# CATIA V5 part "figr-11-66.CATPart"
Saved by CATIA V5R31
Part number: Part2
Bounding box of the stored display mesh (mm): x -101 to 134, y -101.296 to 100.099, z -60.219 to 83.072
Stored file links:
  D:\PROJECTS\Project 2021\US EDITION\CATIA V5 6R 2021\Resources\Part Files\c11_catia_v5_6r2021_prt\figr-11-66.CATPart
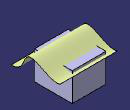
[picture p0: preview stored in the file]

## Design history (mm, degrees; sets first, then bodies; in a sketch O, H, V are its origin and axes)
Set1
  Extrude1: Element1 Sketch2, Lim1 134, Lim2 101, Direction yz-plane
Body1 (main body)
  Sketch1 on yz-plane, origin (0, 0, 0), H (0, 1, 0), V (0, 0, 1)
    line L1 (-70.5879, 56.2311) -> (84.546, 56.2311)
    line L2 (84.546, 56.2311) -> (84.546, -60.2191)
    line L3 (84.546, -60.2191) -> (-70.5879, -60.2191)
    line L4 (-70.5879, -60.2191) -> (-70.5879, 56.2311)
    horizontal: L1 H, L3 H
    vertical: L2 V, L4 V
  Pad1: profile Sketch1, direction (1, 0, 0), length 69, mirrored extent
  Sketch2 on yz-plane, origin (0, 0, 0), H (0, 1, 0), V (0, 0, 1)
    spline S1 through (-101.2957, 16.3509) (-51.8443, 49.0526) (-38.418, 74.5863) (34.1283, 62.9515) (100.0993, 49.0526)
